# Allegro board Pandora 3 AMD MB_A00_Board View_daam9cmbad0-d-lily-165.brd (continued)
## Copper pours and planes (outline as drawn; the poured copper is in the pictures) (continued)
+SMDDR_VTT on TOP (solid shape): 108.08,57.14 108.08,56.32 108.74,55.66 108.74,54.96 108.55,54.77 106.83,54.77 106.24,55.36 106.24,55.92 106.28,56 106.38,56.01 106.91,56.27 106.54,56.74 106.47,56.77 106.44,56.84 106.44,57.11 106.58,57.25 107.96,57.25
+SMDDR_VTT on BOTTOM (solid shape): 18.15,45.65 18.15,44.46 18.1,44.37 17.57,44.39 17.39,44.02 17.52,43.77 17.8,43.68 17.81,43.69 17.83,43.68 18.66,42.85 18.66,41.98 18.58,41.9 18.58,41.38 18.49,41.29 18.46,41.29 18.28,41.33 18.11,41.29 18.1,41.29 18.08,41.29 18.01,41.22 17.87,41.08 17.67,41.08 17.61,41.13 17.59,41.17 17.61,41.21 17.62,41.21 17.87,41.54 17.73,41.93 17.56,42.03 17.33,42.03 17.31,42.05 17.18,42.17 17.18,42.42 16.98,42.63 16.09,42.63 15.91,42.8 15.91,45.64 16.28,46 17.79,46
+SMDDR_VTT on IN1 (solid shape): outline of 353 points within 66.35,32.47 108.81,56.07
+USB_RE_PWR on TOP (solid shape): 266.87,50.36 266.87,49.31 266.85,49.29 266.85,49.03 265.71,47.89 264.28,47.89 264.22,47.95 264.22,50.27 264.38,50.43 264.64,50.43 264.86,50.65 264.86,51.08 265,51.22 266,51.22
+USB_RE_PWR on TOP (solid shape): 269.18,53.83 269.18,53.32 269.02,53.17 268.19,53.17 268.19,53.17 267.9,53.17 267.6,53.47 266.36,53.47 266.33,53.5 266.33,53.65 266.36,53.68 267.64,53.68 267.92,53.95 269.05,53.95
+USB_RE_PWR on BOTTOM (solid shape): 269.18,56.38 269.18,50.78 267.53,49.13 265.62,49.13 265.49,49.26 265.49,49.99 267.81,52.3 267.81,56.8 268.15,57.14 268.42,57.14
+USB_SIDE3_PWR on TOP (solid shape): 273.51,48.03 273.51,47.1 273.35,46.94 270.64,46.94 270.45,46.75 270.24,46.75 270.06,46.93 270.06,47.81 270.47,48.22 273.32,48.22
+USB_SIDE3_PWR on TOP (solid shape): 266.2,47.54 266.2,46.93 266.22,46.81 266.27,46.69 266.28,46.68 266.28,46.49 266.23,46.44 265.61,46.44 265.61,46.44 263.28,46.44 263.2,46.51 263.2,47.45 263.36,47.61 266.13,47.61
+USB_SIDE3_PWR on BOTTOM (solid shape): 275.35,49.59 275.39,49.57 275.4,49.54 275.4,48.8 272.96,46.36 264.21,46.36 263.98,46.6 263.98,47.6 265.12,48.75 267.63,48.75 267.84,48.96 270.14,48.96 270.57,48.54 270.75,48.54 270.82,48.54 270.88,48.54 271.2,48.54 271.34,48.48 271.49,48.46 272.38,48.46 272.52,48.48 272.66,48.53 272.67,48.54 272.74,48.54 273.16,48.96 273.38,48.96 274,49.59
+USB_SIDE3_PWR on IN1 (solid shape): 275.4,49.46 275.4,48.8 272.96,46.36 264.45,46.36 264.17,46.65 264.17,47.65 265.27,48.75 267.64,48.75 267.65,48.75 270.35,48.75 270.57,48.54 270.72,48.54 270.82,48.52 270.92,48.54 271.21,48.54 271.35,48.48 271.49,48.46 272.38,48.46 272.52,48.48 272.65,48.53 272.66,48.54 272.7,48.54 273.75,49.59 275.27,49.59
+USB_SIDE3_PWR on IN2 (solid shape): 277.61,49.43 277.61,48.54 277.48,48.42 276.75,48.42 276.37,48.8 275.4,48.8 272.96,46.36 264.38,46.36 264.19,46.55 264.19,47.69 265.28,48.77 267.67,48.77 267.86,48.96 270.15,48.96 270.59,48.52 271.24,48.52 271.36,48.48 271.49,48.46 272.38,48.46 272.51,48.48 272.63,48.52 272.7,48.52 273.14,48.96 273.38,48.96 274,49.59 275.46,49.59 276.05,49.46 276.58,49.76 277.28,49.76
+USB_SIDE3_PWR on IN4 (solid shape): 275.4,48.8 272.96,46.36 270.52,46.36 270.02,46.87 270.02,48.13 270.35,48.46 272.66,48.46 273.16,48.96 273.38,48.96 274,49.59 275.4,49.59
+V_VDDQ on TOP (solid shape): 25.18,29.93 25.18,29.39 25.31,29.27 28.03,29.27 28.14,29.15 28.14,27.32 28.11,27.28 22.97,27.28 22.77,27.49 22.77,29.88 22.95,30.05 25.06,30.05
+V_VDDQ on TOP (solid shape): outline of 7286 points within 61.39,43.26 83.35,97.69
+V_VDDQ on BOTTOM (solid shape): outline of 254 points within 15.02,27.36 81.47,45.75
+V_VDDQ on SGND (solid shape): outline of 82 points within 22.8,24.62 80.96,92.56
+V_VDDQ on SVCC (solid shape): outline of 99 points within 25.16,24.59 80.96,97.9
+V_VDDQ on SGND1 (solid shape): outline of 92 points within 61.58,42.27 81.39,97.85
+V_VDDQ on SGND2 (solid shape): outline of 91 points within 61.58,42.27 81.42,98.2
+VCHGR on TOP (solid shape): 111.58,12.53 111.58,10.7 111.53,10.65 108.1,10.65 108,10.75 108,12.49 108.11,12.61 111.51,12.61
+VCHGR on BOTTOM (solid shape): 111.97,12.48 111.97,4.87 111.91,4.81 108.26,4.81 108.24,4.83 108.24,8.24 107.97,8.51 106.65,8.51 106.34,8.82 106.34,10.21 106.39,10.26 107.02,10.26 107.02,10.27 107.02,11.63 107.02,11.64 106.37,11.64 106.34,11.67 106.34,12.56 106.4,12.62 111.83,12.62
+VCHGR_P on BOTTOM (solid shape): 97.4,14.62 97.4,14.26 97.59,14.06 99.39,14.06 99.6,13.85 99.6,12.34 99.79,12.15 103.89,12.15 104.28,12.54 105.59,12.54 105.62,12.51 105.62,11.67 105.59,11.63 104.95,11.63 104.92,11.61 104.92,10.28 104.94,10.26 105.61,10.26 105.63,10.24 105.63,8.77 104.99,8.13 98.44,8.13 97.14,8.51 95.8,8.52 95.78,8.52 95.76,8.52 94.77,9.52 94.77,14.6 94.95,14.79 97.23,14.79
+VCHGR_P on IN1 (solid shape): 99.1,11.52 104.58,11.52 105.27,10.82 105.27,8.46 104.6,7.79 96.36,7.79 94.76,9.39 94.76,12.94 95.02,13.21 97.41,13.21
+VGPU_CORE on TOP (solid shape): 144.05,104.76 144.05,104.51 143.79,104.26 143.54,104.26 143.29,104 143.29,103.11 143.54,102.86 143.92,102.86 144.17,102.6 144.17,100.57 143.92,100.32 142.78,100.32 142.65,100.45 142.65,100.7 142.78,100.83 143.03,100.83 143.16,100.95 143.16,101.97 142.4,102.73 142.4,104.64 142.65,104.89 143.92,104.89
+VGPU_CORE on TOP (solid shape): 132.35,81.01 132.63,81.01 133.64,81.01 133.95,81.01 134.79,81.01 135.04,80.76 135.43,80.66 135.69,80.96 135.7,80.99 135.74,81.01 147.38,81.01 148.02,80.37 148.02,76.05 147.43,75.46 141.78,75.46 141.54,75.22 140.55,75.22 140.39,75.06 127.66,75.06 127.41,74.81 126.13,74.81 126,74.94 126,75.39 126.63,76.02 126.63,77.04 126.12,77.55 125.72,77.55 125.63,77.64 125.63,77.98 126.64,79 126.64,79.54 128.2,81.1 129.4,81.1 129.51,81.21 132.14,81.21
+VGPU_CORE on TOP (solid shape): outline of 207 points within 134.14,96.25 144.17,108.4
+VGPU_CORE on BOTTOM (solid shape): 145.1,80.27 145.1,75.67 144.21,74.78 142.99,74.78 142.95,74.8 142.94,74.83 142.94,77.75 142.43,77.75 142.43,74.83 142.42,74.8 142.38,74.78 132.32,74.78 132.29,74.8 132.27,74.83 132.27,77.75 131.76,77.75 131.76,74.83 131.75,74.8 131.71,74.78 126.94,74.78 126.53,75.19 126.53,78.33 126.79,78.59 126.79,79.4 126.99,79.59 131.65,79.59 132.04,79.98 135.08,79.98 135.72,79.34 135.72,78.83 135.82,78.74 136.94,78.74 137.06,78.85 137.06,80.38 137.46,80.79 144.58,80.79
+VGPU_CORE on IN1 (solid shape): outline of 4849 points within 126.59,74.89 145.01,107.8
+VGPU_CORE on SVCC (solid shape): 137.11,107.11 137.15,107.08 137.2,107.07 144.39,107.07 145.25,106.2 145.25,96.58 145.26,96.52 145.29,96.48 145.76,96.02 145.76,91.87 145.67,91.78 145.63,91.65 145.63,87.82 145.65,87.72 145.71,87.63 149.19,84.15 149.19,82.43 147.76,81.01 147.71,80.92 147.69,80.82 147.69,75.37 147.43,75.11 140.52,75.11 140.14,75.52 139.68,75.2 139.21,75.54 138.82,75.11 136.52,75.11 136.08,75.54 135.65,75.11 126.43,75.11 125.9,75.65 125.9,79.4 127.17,80.67 127.22,80.76 127.24,80.86 127.24,107.24 127.35,107.35 130.9,107.35 131.03,107.38 131.12,107.47 136.74,107.47
+VGPU_CORE on IN2 (solid shape): outline of 664 points within 134.58,96.29 144.33,106.03
+VGPU_CORE on IN3 (solid shape): outline of 745 points within 134.61,96.06 144.34,106.24
+VGPU_CORE on IN4 (solid shape): outline of 3017 points within 123.8,75.07 146.29,105.75
+VREF_CA_A0 on TOP (solid shape): outline of 520 points within 81.68,44.85 89.98,54.72
+VREF_CA_B0 on TOP (solid shape): 90.06,55.31 90.06,55.15 89.98,55.07 85,55.07 84.6,55.47 84.18,55.47 83.78,55.07 80.42,55.07 80.27,55.11 80.12,55.09 80.1,55.09 80.07,55.1 79.97,55.2 79.97,55.61 80.07,55.71 83.5,55.71 83.6,55.81 83.6,56.09 83.5,56.19 81.62,56.19 81.52,56.29 81.52,56.77 81.57,56.82 88.55,56.82
AUD_SPK_L+ on TOP (solid shape): 30.75,123.18 30.75,122.43 30.68,122.36 29.87,122.36 29.75,122.24 29.75,121.12 29.62,120.99 28.88,120.99 28.78,121.09 28.78,123.2 30.73,123.2
AUD_SPK_L+ on TOP (solid shape): 14.14,45.35 14.14,43.97 14.14,43.95 14.14,41.23 13.32,40.42 11.37,40.42 11.32,40.47 11.32,41.1 11.39,41.18 12.18,41.18 13.13,42.13 13.13,43.68 12.35,44.46 12.35,45.53 12.55,45.74 13.74,45.74
AUD_SPK_L+ on IN3 (solid shape): 13.11,45.59 13.11,44.61 12.97,44.46 10.89,44.46 10.66,44.69 10.66,45.65 10.85,45.83 12.87,45.83
AUD_SPK_L+ on IN3 (solid shape): 29.59,122.2 29.59,121.01 30.5,120.09 30.5,119.42 30.49,119.38 30.45,119.37 29.18,119.37 28.87,119.68 28.87,122.18 28.95,122.26 29.53,122.26
AUD_SPK_L- on TOP (solid shape): 32.5,123.63 32.5,122.07 31.29,120.87 30.14,120.87 29.95,121.06 29.95,122.02 30.09,122.16 30.81,122.16 30.94,122.28 30.94,123.36 30.63,123.66 28.75,123.66 28.72,123.69 28.72,124.45 28.74,124.46 31.66,124.46
AUD_SPK_L- on TOP (solid shape): 16.45,46.24 16.45,40.8 14.82,39.17 11.39,39.17 11.29,39.27 11.29,39.88 11.34,39.93 13.37,39.93 13.47,40.03 13.48,40.03 14.52,41.07 14.52,43.95 14.52,45.58 13.5,46.6 12.58,46.6 12.4,46.78 12.4,47.81 12.62,48.02 14.66,48.02
AUD_SPK_L- on IN3 (solid shape): 32.05,121.63 32.05,120.38 31.85,120.18 30.96,120.18 29.97,121.17 29.97,122.28 30.43,122.74 30.94,122.74
AUD_SPK_L- on IN3 (solid shape): 14.12,49.58 14.12,47.44 13.46,46.78 12.52,46.78 12.42,46.88 12.42,49.59 12.62,49.79 13.91,49.79
AUD_SPK_R+ on TOP (solid shape): 31.74,127.18 31.74,126.33 31.54,126.13 28.73,126.13 28.68,126.18 28.68,126.93 28.74,126.98 30.45,126.98 30.85,127.39 31.53,127.39
AUD_SPK_R+ on TOP (solid shape): 13.34,37.42 15.3,37.42 15.41,37.32 15.41,36.63 15.13,36.35 13.63,36.35 13.32,36.66 11.37,36.66 11.32,36.71 11.32,37.42 11.34,37.44 13.32,37.44
AUD_SPK_R+ on IN4 (solid shape): 15.69,37.67 15.69,36.63 15.38,36.33 13.56,36.33 13.46,36.43 13.46,37.25 13.63,37.42 14.32,37.42 14.64,37.74 14.64,37.75 14.67,37.77 15.58,37.77
AUD_SPK_R+ on IN4 (solid shape): 33.42,127.15 33.42,125.93 33.24,125.75 31.94,125.75 31.68,126.01 31.59,126.01 31.49,126.11 30.86,126.11 30.71,126.27 30.71,127.18 31.04,127.51 33.06,127.51
AUD_SPK_R- on TOP (solid shape): 31.52,125.67 31.52,124.85 31.41,124.74 31.02,124.74 30.86,124.9 28.76,124.9 28.71,124.95 28.71,125.7 28.73,125.72 30.8,125.72 30.9,125.81 31.37,125.81
AUD_SPK_R- on TOP (solid shape): 15.41,38.54 15.41,38.03 15.18,37.8 13.5,37.8 13.4,37.9 11.34,37.9 11.29,37.95 11.29,38.64 11.32,38.66 13.4,38.66 13.53,38.79 15.15,38.79
AUD_SPK_R- on IN4 (solid shape): 14.51,40.32 14.51,38.42 13.89,37.8 13.45,37.8 13.22,38.03 13.22,40.29 13.37,40.44 14.39,40.44
AUD_SPK_R- on IN4 (solid shape): 31.8,125.27 31.8,122.83 31.78,122.8 31.74,122.78 30.67,122.78 30.1,123.35 30.1,125.05 30.78,125.73 31.33,125.73
CHGR_PHASE on BOTTOM (solid shape): 91.81,15.23 91.81,9.92 91.68,9.8 87.61,9.8 87.56,9.84 87.56,12.15 87.41,12.31 86.13,12.31 85.97,12.46 85.97,15.19 86.13,15.34 91.69,15.34
CHGR_VCC on BOTTOM (solid shape): 72.47,10.63 72.47,9.76 72.31,9.6 71.83,9.6 71.5,9.94 71.5,10.69 71.54,10.74 72.36,10.74
LAN_MCTG on TOP (solid shape): 279.23,110.4 279.23,108.72 279.23,108.7 279.22,108.68 279,108.45 278.82,108.2 277.75,107.09 277.36,105.6 277.36,103.23 276.92,102.8 276.92,96.55 276.59,96.22 275.93,96.22 275.83,96.32 275.83,103.21 276.13,103.51 276.13,107.62 277.77,109.26 277.77,110.86 278.08,111.17 278.46,111.17
LAN_MCTG on BOTTOM (solid shape): 280.94,112.12 280.94,110.01 280.28,109.35 277.91,109.35 277.81,109.45 277.81,111.76 278.27,112.22 280.84,112.22
LGATE_1 on BOTTOM (solid shape): 83.23,139.22 83.23,137.75 83.01,137.52 82.03,137.52 81.78,137.77 81.78,139.12 81.96,139.3 83.16,139.3
LGATE_1 on IN2 (solid shape): 83.81,138.64 83.81,137.5 83.68,137.37 81.85,137.37 81.47,137.75 81.47,137.77 81.47,137.79 81.49,137.93 81.45,138.08 81.45,138.09 81.45,138.97 81.7,139.22 83.22,139.22
LGATE_2 on BOTTOM (solid shape): 74.37,139.22 74.37,137.75 74.15,137.52 73.18,137.52 72.92,137.77 72.92,139.12 73.1,139.3 74.3,139.3
LGATE_2 on IN2 (solid shape): 73.77,140.43 73.81,140.41 73.83,140.38 73.83,139.43 74.33,138.92 74.33,137.93 73.98,137.57 72.58,137.57 72.55,137.59 72.53,137.62 72.53,140.24 72.72,140.43
LGATE_CI on BOTTOM (solid shape): 153.23,62.69 153.23,60.2 153.02,60 152.87,60 152.49,60.38 152.49,62.64 152.67,62.82 153.1,62.82
LGATE_GFX1 on BOTTOM (solid shape): 57.74,139.29 57.74,137.82 57.52,137.6 57.06,137.6 56.93,137.47 56.93,135.34 55.88,134.28 54.56,134.28 54.44,134.41 54.44,138.19 55.61,139.37 57.66,139.37
LGATE_GFX1 on IN2 (solid shape): 56.23,134.68 56.23,133.63 55.14,132.54 53.97,132.54 53.66,132.86 53.66,133.94 54.98,135.26 55.65,135.26
LGATE_GFX2 on BOTTOM (solid shape): 66.89,139.22 66.89,137.75 66.66,137.52 65.44,137.52 65.34,137.62 65.34,139.02 65.62,139.3 66.82,139.3
LGATE_GFX2 on IN3 (solid shape): 66.49,138.66 66.49,138.16 65.98,137.65 64.83,137.65 64.71,137.77 64.71,138.54 65.49,139.32 65.82,139.32
LGATE_GPU1 on BOTTOM (solid shape): 131.07,65.55 131.07,64.18 130.11,63.23 129.48,63.23 129.33,63.37 129.33,65.52 129.58,65.77 130.85,65.77
LGATE_GPU1 on BOTTOM (solid shape): 136.84,65.74 136.84,64.24 135.83,63.23 135.19,63.23 135.19,65.54 135.21,65.57 135.21,65.84 135.52,66.15 136.43,66.15
LGATE_GPU1 on IN2 (solid shape): 140.17,54.92 140.17,54.23 140.5,53.9 140.5,53.17 140.32,52.99 139.64,52.99 137.78,54.84 137.78,55.38 138.55,56.14 138.95,56.14
LGATE_GPU2 on BOTTOM (solid shape): 146.4,65.52 146.4,64.15 145.48,63.23 144.84,63.23 144.84,65.55 144.99,65.7 146.22,65.7
LGATE_GPU2 on BOTTOM (solid shape): 152.08,65.47 152.08,64.12 151.19,63.23 150.56,63.23 150.43,63.36 150.43,65.47 150.64,65.69 151.87,65.69
LGATE_GPU2 on IN2 (solid shape): 145.17,55.07 145.17,54.36 143.98,53.17 143.3,53.17 143.19,53.18 143.09,53.17 141.42,53.17 141.16,53.42 141.16,54.16 141.52,54.51 142.81,54.51 144.11,55.81 144.44,55.81
LGATE_NB on TOP (solid shape): 99.15,142.27 99.15,138.56 99.12,138.54 98.16,138.54 97.88,138.82 97.88,142.27 98.01,142.4 99.02,142.4
LGATE_NB on BOTTOM (solid shape): 100.22,140.21 100.22,138.66 100.06,138.51 98.69,138.51 98.49,138.71 98.49,139.88 99,140.39 100.04,140.39
PHASE_1 on BOTTOM (solid shape): 108.44,142.55 108.46,142.55 108.48,142.53 108.79,142.39 109.1,142.53 109.12,142.55 109.14,142.55 109.31,142.55 109.41,142.45 109.41,142.11 109.31,141.92 109.33,141.7 109.34,141.69 109.33,141.66 108.7,141.03 107.43,141.03 106.92,141.53 106.92,142.37 106.96,142.41 107.97,142.41 108.11,142.55
PHASE_1 on BOTTOM (solid shape): 87.31,137.77 87.8,137.77 87.95,137.77 88.2,137.52 88.2,137.13 87.97,136.9 87.97,136.08 86.49,134.6 85.04,134.6 85.02,134.62 85.02,136.03 84.46,136.03 84.46,134.65 84.44,134.61 84.41,134.6 83,134.6 82.87,134.73 82.87,135.09 82.87,135.14 82.87,135.94 82.87,135.98 82.87,136.03 82.87,136.83 82.87,136.87 82.87,137.01 83.25,137.39 83.38,137.39 83.5,137.52 83.5,138.03 83.76,138.28 86.81,138.28
PHASE_2 on BOTTOM (solid shape): 78.89,137.43 78.89,135.32 78.04,134.47 76.21,134.47 76.18,134.49 76.16,134.52 76.16,136.03 75.6,136.03 75.6,134.52 75.59,134.49 75.55,134.47 74.16,134.47 74.12,134.49 74.11,134.52 74.11,137.27 74.23,137.39 74.61,137.39 74.87,137.65 74.87,138.16 74.99,138.28 78.04,138.28
PHASE_2 on BOTTOM (solid shape): 108.29,146.64 108.29,146.63 108.38,146.39 108.58,146.24 108.6,146.24 109.46,145.38 109.5,145.34 109.55,145.31 110,144.86 110,144.51 109.98,144.47 109.94,144.46 109.8,144.46 109.77,144.48 109.76,144.5 109.44,144.85 109,144.65 108.98,144.63 108.96,144.62 108.61,144.62 107.41,145.83 107.41,146.73 107.48,146.8 108.13,146.8
PHASE_CI on BOTTOM (solid shape): 155.97,67.12 155.97,66 156.33,65.64 156.39,65.64 157.16,65.64 157.29,65.51 157.29,63.73 156.78,63.23 152.69,63.23 152.5,63.42 152.5,65.21 152.21,65.5 152.21,65.53 151.92,65.81 151.9,65.81 151.81,65.9 150.42,65.9 149.16,67.16 149.16,68.76 149.47,69.06 154.03,69.06
PHASE_GFX1 on BOTTOM (solid shape): 61.79,137.9 61.79,134.65 61.77,134.61 61.74,134.6 60.4,134.6 60.37,134.61 60.35,134.65 60.35,136.03 59.79,136.03 59.79,134.65 59.78,134.61 59.74,134.6 57.47,134.6 57.09,134.98 57.09,136.38 58.1,137.39 58.1,137.9 58.48,138.28 61.41,138.28
PHASE_GFX2 on BOTTOM (solid shape): 70.78,138.18 70.78,137.37 71.06,137.09 71.06,135.4 71.05,135.37 71.03,135.35 70.91,135.27 70.83,135.14 70.82,135.13 70.17,134.47 68.39,134.47 68.36,134.49 68.34,134.52 68.34,136.03 67.78,136.03 67.78,134.52 67.77,134.49 67.73,134.47 66.23,134.47 66.1,134.61 66.07,134.69 66.11,134.76 66.28,135.12 66.09,135.47 66.04,135.55 66.28,136 66.04,136.44 66.09,136.53 66.26,136.74 66.26,137.01 66.26,137.04 66.28,137.06 66.49,137.27 67.12,137.27 67.37,137.52 67.37,138.16 67.5,138.28 70.68,138.28
PHASE_GPU1 on BOTTOM (solid shape): 131.71,70.29 131.75,70.27 131.76,70.24 131.76,67.75 132.27,67.75 132.27,70.24 132.29,70.27 132.32,70.29 134.19,70.29 134.81,69.67 134.81,64.37 134.68,64.24 131.5,64.24 131.44,64.3 131.44,65.5 130.88,66.06 130.77,66.06 130.76,66.07 129.34,66.07 128.93,65.67 128.93,64.3 128.87,64.24 125.79,64.24 125.74,64.29 125.74,66.35 126.63,67.24 126.63,68.2 128.72,70.29
PHASE_GPU1 on BOTTOM (solid shape): 139.23,54.03 139.24,54 139.24,53.99 139.29,53.62 139.61,53.43 139.63,53.42 139.75,53.31 139.75,53.29 139.77,53.18 139.82,53.08 139.83,53.07 139.83,53.03 139.71,52.91 139.56,52.91 138.88,53.6 138.24,53.6 137.99,53.35 137.52,53.35 137.1,53.77 137.1,54.89 137.2,55 138.27,55
PHASE_GPU2 on BOTTOM (solid shape): 142.38,71.1 142.42,71.08 142.43,71.05 142.43,67.75 142.94,67.75 142.94,71.05 142.95,71.08 142.99,71.1 147.21,71.1 147.24,71.08 147.26,71.05 147.26,68.69 150.18,65.77 150.18,64.4 150.01,64.24 146.85,64.24 146.71,64.38 146.71,65.6 146.39,65.92 144.85,65.92 144.55,65.61 144.55,64.34 144.41,64.2 141.04,64.2 140.61,64.64 140.61,65.32 140.02,65.91 140.02,70.72 140.4,71.1
PHASE_NB on BOTTOM (solid shape): 104.59,138.92 104.59,136.65 103.43,135.49 102.09,135.49 102.06,135.5 102.04,135.54 102.04,136.91 101.48,136.91 101.48,135.54 101.47,135.5 101.43,135.49 97.6,135.49 97.35,135.74 97.35,136.12 97.47,136.25 98.11,136.25 98.51,136.66 98.51,137.98 98.79,138.26 100.11,138.26 100.52,138.66 100.52,139.04 100.78,139.3 104.2,139.3
PHASE_NB on BOTTOM (solid shape): 111.63,149.78 111.63,148.96 111.62,148.93 111.59,148.91 111.24,148.5 111.56,148.07 111.58,148.06 112.09,147.55 112.09,147.04 112.07,147 112.04,146.99 111.67,146.99 111.25,147.4 111.24,147.4 111.23,147.43 110.97,147.6 110.67,147.56 110.64,147.55 110.61,147.56 109.97,148.2 109.97,149.83 110.06,149.92 111.49,149.92
REG_OUT on TOP (solid shape): 272.67,86.79 273.3,86.79 273.87,86.22 273.88,86.2 273.88,86.18 274.01,85.79 274.4,85.66 274.42,85.66 274.44,85.64 274.69,85.4 274.69,85.08 274.67,85.02 274.66,84.97 274.66,84.67 274.67,84.61 274.69,84.56 274.69,83.24 273.75,82.3 273.47,82.3 273.27,82.5 273.27,84.82 272.38,85.7 272.38,86.77 272.4,86.8 272.67,86.8
TP_PWR_EN on BOTTOM (solid shape): 178.72,36.55 178.72,34.97 178.52,34.78 174.31,34.78 174.23,34.85 174.23,36.25 174.33,36.35 178.19,36.35 178.4,36.56 178.71,36.56
TRA_V_DAC on TOP (solid shape): 269.96,105.32 269.96,104.83 269.86,104.73 268.13,104.73 268.01,104.86 268.01,105.37 268.08,105.44 269.84,105.44
TRA_V_DAC on TOP (solid shape): 270.6,96.88 270.6,96.4 270.47,96.27 269.51,96.27 269.36,96.42 269.36,96.86 269.86,97.36 270.12,97.36
TRA_V_DAC on BOTTOM (solid shape): 269.84,105.7 269.84,104.81 269.56,104.53 269.33,104.53 268.44,103.64 266.69,103.64 266.51,103.82 266.51,105.57 266.74,105.8 269.73,105.8
TRA_V_DAC on BOTTOM (solid shape): 268.92,97.7 269.71,97.7 269.72,97.68 270.27,97.68 270.57,97.38 270.57,96.35 270.37,96.15 270.35,96.15 270.28,96.14 270.21,96.12 269.88,96.12 269.87,96.12 269.72,96.15 269.56,96.12 269.55,96.12 266.94,96.12 266.91,96.13 266.89,96.17 266.89,96.83 266.91,96.87 266.94,96.88 267.73,96.88 267.76,96.92 267.76,97.35 267.73,97.39 266.94,97.39 266.91,97.41 266.89,97.44 266.89,98.13 266.91,98.16 266.94,98.18 268.44,98.18
TRA_V_DAC on IN2 (solid shape): 270.01,105.49 270.01,104.65 269.84,104.48 269.07,104.48 268.95,104.35 268.95,103.92 268.93,103.82 268.95,103.72 268.95,97.77 269.15,97.57 269.76,97.57 269.76,97.56 270.36,97.56 270.54,97.39 270.54,96.47 270.29,96.22 268.06,96.22 267.55,96.73 267.55,105.42 267.83,105.7 269.81,105.7
VREFC_A0 on BOTTOM (solid shape): 125.65,133.58 126.91,133.58 126.95,133.57 126.96,133.53 126.96,133.35 126.96,133.33 126.84,133.2 126.8,133.05 126.79,133.03 126.64,132.88 126.63,132.87 123.53,132.87 123.31,133.1 123.31,133.88 123.71,134.28 124.95,134.28
VREFD1_B0 on TOP (solid shape): 179.26,115.02 179.29,115 179.31,114.97 179.31,112.4 179.29,112.36 179.26,112.35 178.91,112.35 178.83,112.37 178.76,112.37 177.75,112.37 177.67,112.37 177.6,112.35 176.42,112.35 176.29,112.48 176.29,113.14 176.49,113.34 177.48,113.34 177.58,113.44 177.58,113.52 177.66,113.65 177.69,113.81 177.69,114.62 177.65,114.66 177.64,114.69 177.65,114.73 177.87,114.94 177.89,114.96 177.91,114.96 178.02,114.97 178.12,115.02
VREFD2_B1 on TOP (solid shape): 178.45,92.96 178.45,92.47 178.38,92.4 178.38,89.56 178.3,89.49 177.75,89.49 177.6,89.65 177.6,90.65 177.75,90.8 177.75,93.03 177.8,93.08 178.33,93.08
N4259362 on TOP (solid shape): 60.01,7.47 60.01,6.96 60.26,6.71 60.9,6.71 61.15,6.46 61.15,5.57 60.9,5.31 58.99,5.31 58.36,5.95 58.36,7.47 58.48,7.6 59.88,7.6
N5524290 on BOTTOM (solid shape): 61.86,8.67 61.86,7.83 61.81,7.78 61.2,7.78 61.15,7.73 61.15,6.43 61.2,6.38 61.86,6.38 61.89,6.36 61.89,4.61 61.82,4.54 57.8,4.54 57.63,4.71 57.63,7.33 57.82,7.52 59.25,7.52 59.7,7.52 60.16,7.98 60.16,8.45 60.42,8.7 61.82,8.7
N21319071 on BOTTOM (solid shape): 89.78,139.27 89.78,137.22 89.7,137.14 88.99,137.14 88.82,137.3 88.82,137.66 88.56,137.93 87.72,137.93 87.67,137.98 87.67,138.36 87.72,138.41 88.46,138.41 88.71,138.66 88.71,139.27 88.81,139.37 89.68,139.37
N21319549 on TOP (solid shape): 81.17,135.64 81.17,134.8 80.25,133.89 79.19,133.89 78.55,134.52 78.55,135.21 78.6,135.26 79.21,135.26 79.64,135.69 81.12,135.69
N21319706 on BOTTOM (solid shape): 98.18,138.44 98.18,136.63 97.96,136.4 96.84,136.4 96.51,136.73 96.51,138.33 96.74,138.56 98.06,138.56
N21319821 on BOTTOM (solid shape): 106.82,148.82 106.82,145.95 106.8,145.93 106.01,145.93 105.88,146.06 105.88,148.85 106.16,149.13 106.52,149.13
N21319902 on BOTTOM (solid shape): 106.44,142.35 106.44,139.81 105.83,139.2 105.45,139.2 105.3,139.35 105.3,142.35 105.45,142.5 106.29,142.5
N21320002 on BOTTOM (solid shape): 111.75,151.01 111.75,150.5 111.57,150.32 108.52,150.32 108.32,150.53 108.32,150.96 108.52,151.16 111.6,151.16
N21323581 on BOTTOM (solid shape): 42.66,120.36 42.66,119.99 43.14,119.51 43.14,119.26 42.97,119.08 42.48,119.08 41.97,119.59 41.69,119.59 41.49,119.79 41.49,120.19 42.33,120.19 42.33,120.39 41.49,120.39 41.49,120.59 42.43,120.59
N21323587 on BOTTOM (solid shape): 43.09,121.82 43.09,120.78 42.99,120.68 42.72,120.68 42.68,120.72 42.44,120.72 42.41,120.76 42.36,120.76 42.33,120.79 42.33,120.79 41.47,120.79 41.43,120.8 41.42,120.84 41.42,120.94 41.43,120.98 41.47,120.99 42.33,120.99 42.33,121.19 41.47,121.19 41.43,121.2 41.42,121.24 41.42,121.34 41.43,121.38 41.47,121.39 42.33,121.39 42.33,121.59 41.47,121.59 41.43,121.6 41.42,121.64 41.42,121.74 41.42,121.77 41.45,121.79 41.46,121.8 41.49,121.79 42.33,121.79 42.35,121.81 42.42,121.81 42.48,121.87 43.04,121.87
N21324846 on BOTTOM (solid shape): 38.7,128.3 38.7,127.56 38.65,127.51 35.98,127.51 35.88,127.61 35.88,128.17 36.74,129.04 37.96,129.04
N21324850 on TOP (solid shape): 56.71,136.43 57.24,136.43 57.34,136.33 57.34,135.82 57.28,135.76 56.74,135.76 56.53,135.54 56.53,134.9 56.41,134.79 55.96,134.79 55.89,134.85 55.89,135.11 55.53,135.48 55.19,135.48 55,135.67 55,137.01 55.21,137.22 55.92,137.22
N21328341 on TOP (solid shape): 136.2,36.85 136.2,35.37 136.28,35.29 136.28,34.3 136.18,34.19 134.94,34.19 134.53,34.6 134.53,36.58 134.89,36.94 136.11,36.94
N21328349 on BOTTOM (solid shape): 141.61,38.93 141.61,37.79 141.82,37.58 141.82,36.9 141.93,36.78 142.54,36.78 142.65,36.66 142.65,33.23 142.4,32.97 141.66,32.97 141.55,33.08 141.55,33.31 141.55,33.35 141.55,33.41 141.55,33.45 141.55,35.95 140.53,35.95 140.51,35.97 140.46,36 140.4,36.02 140.35,36.03 140.29,36.04 140.23,36.03 140.17,36.02 140.12,36 140.06,35.98 140.03,35.95 139.9,35.95 139.64,35.69 139.64,34.17 139.38,33.91 137.61,33.91 137.1,34.42 137.1,36.19 141.34,36.19 141.34,36.43 140.73,36.43 140.73,36.19 137.1,36.19 137.1,38.23 138.11,39.25 141.29,39.25
N21328385 on BOTTOM (solid shape): 142.94,40.74 142.94,39.73 142.81,39.6 140.15,39.6 139.89,39.86 139.89,40.75 140.48,41.33 142.35,41.33
N21337006 on BOTTOM (solid shape): 145.02,56.14 145.02,55.43 144.95,55.35 142.82,55.35 142.51,55.66 142.51,55.66 142.51,56.67 142.79,56.95 144.21,56.95
N21337030 on TOP (solid shape): 141.52,67.49 141.52,66.53 140.86,65.87 139.54,65.87 139.43,65.97 139.43,67.7 139.64,67.9 141.11,67.9
N21337282 on BOTTOM (solid shape): 138.27,56.32 138.27,55.61 138.04,55.38 135.12,55.38 134.94,55.55 134.94,56.11 135.5,56.67 137.91,56.67
N21337361 on TOP (solid shape): 154.39,65.05 154.39,62.46 154.22,62.29 153.25,62.29 153.05,62.49 153.05,64.9 153.3,65.16 154.29,65.16
N21337426 on BOTTOM (solid shape): 148.73,56.22 148.73,55.55 148.53,55.35 145.58,55.35 145.48,55.45 145.48,56.23 145.66,56.41 148.54,56.41
N21339411 on BOTTOM (solid shape): 165.8,69.7 165.8,68.94 165.29,68.43 165.29,67.67 165.16,67.54 164.02,67.54 163.89,67.67 163.89,69.58 164.15,69.83 165.67,69.83
N21339426 on BOTTOM (solid shape): 174.26,69.87 174.26,65.76 173.96,65.45 172.82,65.45 172.19,64.82 171.99,64.82 171.81,64.64 171.78,64.62 171.73,64.6 171.7,64.56 171.66,64.53 171.64,64.5 171.62,64.48 171.61,64.48 170.91,64.48 170.81,64.39 170.81,63.82 170.68,63.68 167.38,63.68 167.08,63.98 167.08,64.59 167.31,64.82 169.86,64.82 169.87,64.93 169.88,64.94 170.48,64.95 170.48,65.56 170.23,65.56 170.23,64.95 169.98,64.95 169.98,65.54 169.99,65.57 170,65.58 170.04,65.59 170.27,65.81 170.27,67.39 170,67.66 165.66,67.66 165.54,67.78 165.54,68.31 166.05,68.81 166.05,70.07 166.31,70.34 173.8,70.34
N21339465 on BOTTOM (solid shape): 176.21,66.65 176.21,65.26 175.32,64.37 174.69,64.37 174.56,64.5 174.56,66.78 174.69,66.91 175.96,66.91
N23370536 on BOTTOM (solid shape): 33.13,108.83 33.13,108.36 33.34,108.15 33.34,107.62 33.42,107.54 33.43,107.54 33.55,107.42 34.17,107.42 34.2,107.39 34.2,107.16 33.4,107.16 33.39,107.17 32.69,107.17 32.6,107.08 31.47,107.08 31.41,107.14 31.41,109.43 31.48,109.5 32.46,109.5
N23370587 on BOTTOM (solid shape): 37.96,106.43 37.96,105.66 37.88,105.58 37.78,105.58 37.74,105.6 37.68,105.61 37.62,105.62 37.55,105.62 37.49,105.61 37.43,105.6 37.39,105.58 35.25,105.58 35.13,105.46 35.13,104.73 34.97,104.58 34.97,103.66 35.33,103.3 35.62,103.3 35.66,103.28 35.71,103.27 35.77,103.26 35.82,103.27 35.88,103.27 35.93,103.29 35.96,103.3 35.98,103.3 36.08,103.2 36.08,99.88 35.88,99.67 31.85,99.67 31.2,100.33 31.2,103.64 31.66,104.11 31.66,104.84 34.87,104.84 34.87,105.45 34.63,105.45 34.63,104.84 31.66,104.84 31.66,104.93 31.94,105.21 32.86,105.21 33.07,105.42 33.12,105.42 33.17,105.43 33.22,105.45 33.27,105.47 33.31,105.5 33.35,105.53 33.39,105.57 33.42,105.62 33.44,105.66 33.45,105.71 33.46,105.77 33.46,105.81 33.57,105.92 34.25,105.92 34.3,105.97 34.3,106.68 34.31,106.71 34.33,106.73 34.35,106.73 37.66,106.73
N23379108 on TOP (solid shape): 37.38,99.95 37.38,99.04 36.89,98.56 34.89,98.56 34.66,98.79 34.66,99.98 34.71,100.03 37.3,100.03
N23379126 on BOTTOM (solid shape): 31.13,106.25 31.13,103.92 31,103.79 29.93,103.79 29.55,104.17 29.55,106.13 29.81,106.38 31,106.38
N23726703 on TOP (solid shape): 132.25,67.34 132.25,65.97 132.09,65.82 131.2,65.82 130.95,66.07 129.99,66.07 129.83,66.22 129.83,67.26 130.21,67.65 131.94,67.65
N24882676 on BOTTOM (solid shape): 58.64,125.96 59.68,125.96 59.78,125.86 59.78,124.8 59.73,124.74 57.67,124.74 57.44,124.52 57.01,124.52 56.73,124.8 56.73,126.19 56.88,126.34 58.26,126.34
N24882949 on BOTTOM (solid shape): 126.2,42.98 126.2,41.92 126.18,41.89 125.72,41.89 125.54,41.71 125.54,41.25 125.41,41.13 124.68,41.13 124.12,41.69 123.31,41.69 123.15,41.84 123.15,42.73 123.28,42.85 124.75,42.85 124.93,43.03 126.15,43.03
N30992906 on BOTTOM (solid shape): 90.65,8.27 90.65,6.38 89.24,6.38 89.17,6.46 89.17,7.35 89.4,7.57 89.6,7.57 89.93,7.9 89.93,8.39 89.98,8.44 90.49,8.44
N124462712 on TOP (solid shape): 137.35,7.85 137.35,5.57 136.97,5.19 135.95,5.19 135.83,5.31 135.83,7.85 136.08,8.11 137.1,8.11
N124463006 on BOTTOM (solid shape): 177.61,10.77 177.61,9.28 176.87,8.54 176.34,8.54 175.91,8.97 175.22,8.97 175.06,9.14 175.06,9.64 176.26,10.85 177.53,10.85
N124463039 on BOTTOM (solid shape): 155.23,12.45 155.23,9.38 155.08,9.23 154.22,9.23 154.14,9.3 154.14,11.71 154.47,12.04 154.47,12.45 154.62,12.6 155.08,12.6

Small or netless copper shapes (teardrops, artwork), in the pictures only: 53 on TOP, 1332 on BOTTOM, 1 on IN1, 8 on IN2

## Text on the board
Ref Des/Silkscreen Bottom: RTC BATT | M.2 NGFF | TM4 | HDD | DCIN | TM1 | BATT | TM2 | LCD | M.2 SSD | TM7 | CardReader | USB | HDMI | LAN | TM6 | DIMM B | DIMM A | DAAM9CMBAD0 REV:D | DDR4 ONLY
User.Comments: 83.0x126.0
Ref Des/Silkscreen Top: A | B | I/O POWER | PROCESSOR | FAN | I/O CONN | KB | SPK | TM5 | KB B/L | VIDEO FAN | T/P | LED | PWR_BTN | DELL:WVX00 | MODEL:AM9C | DAAM9CMBAD0 REV:D
BODY_CENTER: CHANGE DESCRIPTION AS PDC REQUEAST
User.9: 1. ADD R
User.10: 2. ADD R
User.13: +1.5V_VDD | +PWR_SRC | +V_VDDQ | GND | +VDDCR_GFX | +VDDCR_CPU | +VDDCR_NB | +VGPU_CORE
User.30: REV:A-4
User.32: +V_VDDQ | GND
User.33: +1.5v_vdd | GND | +VDDCR_GFX | +V_VDDQ | +VDDCR_CPU | +PWR_SRC | +VDDCR_NB | +VGPU_CORE
User.34: +V_VDDQ | GND
User.35: +V_VDDQ | GND
User.36: +V_VDDQ | GND
User.37: +V_VDDQ | GND
User.38: +V_VDDQ | GND
User.45: No Route Under Component:Sep 09 12:13:57 2016 | PadStack_Check:Sep 09 11:33:00 2016 | TP check:Sep 09 11:42:16 2016 | XY-Check acute:Sep 09 12:05:37 2016 | XY-Check cline width:Sep 09 12:12:04 2016 | XY-Check rotation:Sep 10 16:16:09 2016 | XY-Check txt overlap:Sep 10 16:06:30 2016 | XY-Check txt:Sep 10 16:27:17 2016 | XY-Create nettxt:Aug 25 18:29:05 2016 | XY-Create plane:Sep 09 14:27:36 2016 | XY-Cross plane-BOTTOM-SGND2:Sep 09 12:08:36 2016 | XY-Cross plane-IN1-SGND:Sep 09 12:08:07 2016 | XY-Cross plane-IN1-SVCC:Sep 09 12:07:58 2016 | XY-Cross plane-IN2-SVCC:Sep 09 12:08:13 2016 | XY-Cross plane-IN3-SGND1:Sep 09 12:08:18 2016 | XY-Cross plane-IN4-SGND1:Sep 09 12:08:30 2016 | XY-Cross plane-IN4-SGND2:Sep 09 12:08:22 2016 | XY-Cross plane-TOP-SGND:Sep 09 12:07:46 2016 | XY-Dxf to pin check:Sep 09 11:38:32 2016 | XY-Etch cross-IN2-IN3:Sep 09 12:08:12 2016 | XY-Etch ref-BOTTOM-SGND2:Sep 09 12:08:46 2016 | XY-Etch ref-IN1-SGND:Sep 09 12:08:12 2016 | XY-Etch ref-IN1-SVCC:Sep 09 12:08:07 2016 | XY-Etch ref-IN2-SVCC:Sep 09 12:08:18 2016 | XY-Etch ref-IN3-SGND1:Sep 09 12:08:22 2016 | XY-Etch ref-IN4-SGND1:Sep 09 12:08:35 2016 | XY-Etch ref-IN4-SGND2:Sep 09 12:08:29 2016 | XY-Etch ref-TOP-SGND:Sep 09 12:07:57 2016 | XY-Excess check:Sep 08 15:12:08 2016 | XY-Mask check:Sep 09 12:14:23 2016 | XY-NO Route Under Component:Sep 09 12:13:57 2016 | XY-Norefdes:Sep 10 16:15:57 2016 | XY-Outline check:Sep 09 12:14:03 2016 | XY-PadStack_Check:Sep 09 11:33:00 2016 | XY-Plane net check:Sep 09 11:42:53 2016 | XY-Prop check:Sep 09 12:07:38 2016 | XY-Symbol cross:Sep 09 11:55:12 2016 | XY-TP check:Sep 09 11:42:16 2016 | XY-shape min check:Sep 09 11:31:49 2016 | XY-via check:Sep 09 12:12:40 2016 | check acute:Sep 09 12:05:37 2016 | check cline width:Sep 09 12:12:04 2016 | check rotation:Sep 10 16:16:09 2016 | check txt overlap:Sep 10 16:06:30 2016 | check txt:Sep 10 16:27:17 2016 | create plane:Sep 09 14:27:36 2016 | cross plane-BOTTOM-SGND2:Sep 09 12:08:36 2016 | cross plane-IN1-SGND:Sep 09 12:08:07 2016 | cross plane-IN1-SVCC:Sep 09 12:07:58 2016 | cross plane-IN2-SVCC:Sep 09 12:08:13 2016 | cross plane-IN3-SGND1:Sep 09 12:08:18 2016 | cross plane-IN4-SGND1:Sep 09 12:08:30 2016 | cross plane-IN4-SGND2:Sep 09 12:08:22 2016 | cross plane-TOP-SGND:Sep 09 12:07:46 2016 | dxf to pin check:Sep 09 11:38:32 2016 | etch cross-IN2-IN3:Sep 09 12:08:12 2016 | etch ref-BOTTOM-SGND2:Sep 09 12:08:46 2016 | etch ref-IN1-SGND:Sep 09 12:08:12 2016 | etch ref-IN1-SVCC:Sep 09 12:08:07 2016 | etch ref-IN2-SVCC:Sep 09 12:08:18 2016 | etch ref-IN3-SGND1:Sep 09 12:08:22 2016 | etch ref-IN4-SGND1:Sep 09 12:08:35 2016 | etch ref-IN4-SGND2:Sep 09 12:08:29 2016 | etch ref-TOP-SGND:Sep 09 12:07:57 2016 | norefdes:Sep 10 16:15:57 2016 | outline check:Sep 09 12:14:03 2016 | plane net check:Sep 09 11:42:53 2016 | prop check:Sep 09 12:07:38 2016 | shape min check:Sep 09 11:31:49 2016 | symbol cross:Sep 09 11:55:12 2016 | via check:Sep 09 12:12:40 2016 | PT_TOP | PT_BOT | FIGURE | TYPE | Oblong | Circle | SIZE | 67.0x24.0 | 71.0x31.0 | 75.0x24.0 | 79.0x24.0 | 100.0x31.0 | 126.0x83.0 | 10.0 | 14.0 | 20.0 | 30.0 | 31.0 | 35.0 | 43.0 | 83.0 | 94.0 | 150.0 | 197.0 | 37.0 | 38.0 | 47.0 | 63.0 | 67.0 | DRILL CHART: TOP to BOTTOM | ALL UNITS ARE IN MILS | PLATED | NON-PLATED | ROTATION | 0.000 | 90.000 | - | QTY | 4 | 2 | 1 | 18 | 4718 | 23 | 1344 | 19 | 9 | 8 | 11 | 5 | 3 | 6161 | TOTAL HOLES:
